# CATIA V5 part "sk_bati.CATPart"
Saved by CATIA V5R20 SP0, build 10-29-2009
Part number: sk_bati
Publications: "Point.4", "Point.5", "Point.7", "Droite.1", "Droite.2", "Droite.3", "Droite.4", "Plan.1", "Plan.2"
Bounding box of the stored display mesh (mm): x -20 to 20, y 0 to 150, z 0 to 10
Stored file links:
  D:\Dropbox\IAO_2011\MMS_GR2\IAO_2011_1495_fpittorino\fpittorino_IAO\IAO_2011_1495_fpittorino\sk_bati.CATPart
  D:\Dropbox\IAO_2011\MMS_GR2\IAO_2011_1495_fpittorino\fpittorino_IAO\IAO_2011_1495_fpittorino\Product3.CATProduct
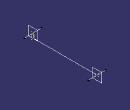
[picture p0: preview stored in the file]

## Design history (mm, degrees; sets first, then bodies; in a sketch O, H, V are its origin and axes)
Set1
  Point1 to Point3: linked copy from another document
Body1 (main body)
  Point4: (0, 0, 0), relative to Point1
  Point5: (0, 0, 0), relative to Point2
  Point6: (0, 0, 0), relative to Point3
  Line1: type PtPt, FirstPoint Point5, SecondPoint Point6
  Line2: type PtPt, FirstPoint Point4, SecondPoint Point6
  Line3: type Normal, RefPoint Point4, RefSkin yz-plane, Start -20, End 20
  Line4: type Normal, RefPoint Point5, RefSkin yz-plane, Start -20, End 20
  Plane1: type Normal, Curve Line4, RefPoint Point5
  Plane2: type Normal, Curve Line3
